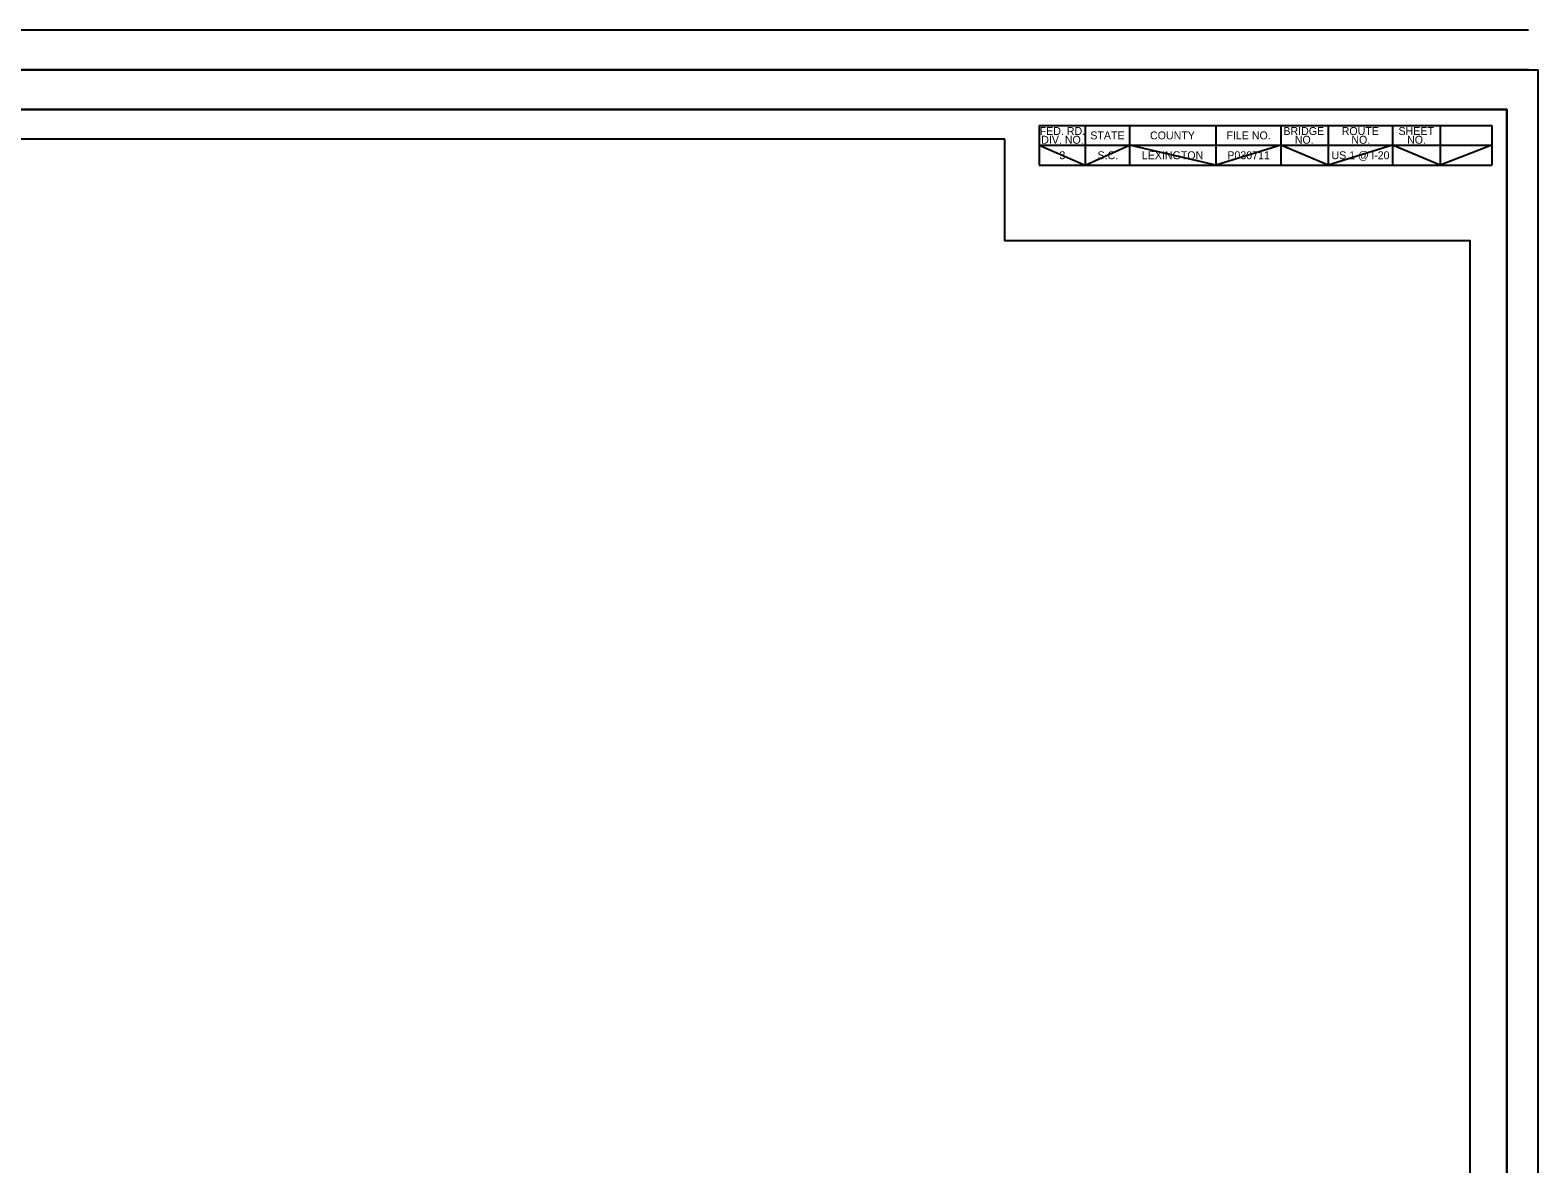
# Model space of a CAD drawing. Extents: x 4999.3 to 5035.3, y 4994.5 to 5023.
# Drawn here: x 5016.34 to 5035.32, y 5008.73 to 5023 of the extents above; entities that cross this region are included whole.
import ezdxf

# ---------------------------------------------------------------- set-up
doc = ezdxf.new("R2010")
doc.units = 0
for name, color, linetype in [('Level 51', 7, 'Continuous'), ('RD_SHT_Bndy', 7, 'Continuous'), ('RD_SHT_IplotShp', 7, 'Continuous'), ('RD_SHT_Misc1', 7, 'Continuous'), ('RD_SHT_Misc4', 7, 'Continuous'), ('RD_SHT_ShtClip', 7, 'Continuous'), ('RD_SHT_Snap', 7, 'Continuous')]:
    doc.layers.add(name, color=color, linetype=linetype)

msp = doc.modelspace()

# ---------------------------------------------------------------- linework, layer by layer
at = {"layer": 'Level 51'}
msp.add_line((5034.09, 5021.3), (5033.49, 5021.55), dxfattribs=at)
at = {"layer": 'RD_SHT_Bndy'}
for p in [(5001.43, 5022), (5034.93, 5001)]:
    msp.add_line(p, (5034.93, 5022), dxfattribs=at)
at = {"layer": 'RD_SHT_IplotShp'}
for points in [[(4999.319, 5022.5), (5035.319, 5022.5), (5035.319, 5000.5), (4999.319, 5000.5)], [(5034.93, 5022), (5001.43, 5022), (5001.43, 5001), (5034.93, 5001)]]:
    msp.add_lwpolyline(points, close=True, dxfattribs=at)
at = {"layer": 'RD_SHT_Misc1'}
for p, q in [((5035.201, 5022.999), (5000.001, 5023)), ((5035.201, 5022.5), (5000.001, 5022.5))]:
    msp.add_line(p, q, dxfattribs=at)
at = {"layer": 'RD_SHT_Misc4'}
for p, q in [((5029.041, 5021.8), (5029.041, 5021.3)), ((5029.041, 5021.8), (5034.74, 5021.8)), ((5029.621, 5021.8), (5029.621, 5021.3)), ((5030.18, 5021.8), (5030.18, 5021.3)), ((5031.266, 5021.8), (5031.266, 5021.3)), ((5032.082, 5021.8), (5032.082, 5021.3)), ((5032.678, 5021.8), (5032.678, 5021.3)), ((5033.49, 5021.8), (5033.49, 5021.3)), ((5034.09, 5021.8), (5034.09, 5021.3)), ((5034.74, 5021.8), (5034.74, 5021.3)), ((5029.041, 5021.55), (5029.621, 5021.55)), ((5029.621, 5021.55), (5030.18, 5021.55)), ((5030.18, 5021.55), (5031.266, 5021.55)), ((5031.266, 5021.55), (5032.082, 5021.55)), ((5032.082, 5021.55), (5032.678, 5021.55)), ((5032.678, 5021.55), (5033.49, 5021.55)), ((5033.49, 5021.55), (5034.09, 5021.55)), ((5034.09, 5021.55), (5034.74, 5021.55)), ((5029.041, 5021.3), (5034.74, 5021.3))]:
    msp.add_line(p, q, dxfattribs=at)
at = {"layer": 'RD_SHT_ShtClip'}
msp.add_line((5034.74, 5021.55), (5034.09, 5021.3), dxfattribs=at)
msp.add_lwpolyline([(5028.611, 5021.626), (5003.594, 5021.626), (5003.594, 5021.356), (5002.034, 5021.356), (5002.034, 5003.533), (5034.467, 5003.533), (5034.467, 5020.348), (5028.611, 5020.348)], close=True, dxfattribs=at)
at = {"layer": 'RD_SHT_Snap'}
for p, q in [((5029.041, 5021.55), (5029.621, 5021.3)), ((5029.621, 5021.3), (5030.18, 5021.55)), ((5031.266, 5021.3), (5030.18, 5021.55)), ((5032.082, 5021.55), (5031.266, 5021.3)), ((5032.678, 5021.3), (5032.082, 5021.55)), ((5033.49, 5021.55), (5032.678, 5021.3)), ((5034.09, 5021.3), (5033.49, 5021.55))]:
    msp.add_line(p, q, dxfattribs=at)
msp.add_lwpolyline([(5001.43, 5022), (5034.93, 5022), (5034.93, 5001), (5001.43, 5001)], close=True, dxfattribs=at)

# ---------------------------------------------------------------- texts
at = {"layer": 'RD_SHT_Misc4'}
for s, p in [('FED. RD.', (5029.048, 5021.68)), ('BRIDGE', (5032.116, 5021.68)), ('ROUTE', (5032.85, 5021.68)), ('SHEET', (5033.565, 5021.68)), ('DIV. NO.', (5029.067, 5021.57)), ('STATE', (5029.685, 5021.625)), ('COUNTY', (5030.437, 5021.625)), ('FILE NO.', (5031.399, 5021.625)), ('NO.', (5032.259, 5021.57)), ('NO.', (5032.971, 5021.57)), ('NO.', (5033.673, 5021.57)), ('3', (5029.296, 5021.375)), ('S.C.', (5029.776, 5021.375)), ('LEXINGTON', (5030.334, 5021.375)), ('P030711', (5031.41, 5021.375)), ('US 1 @ l-20', (5032.721, 5021.375))]:
    msp.add_text(s, height=0.1, dxfattribs=at).set_placement(p)

doc.saveas('drawing.dxf')
